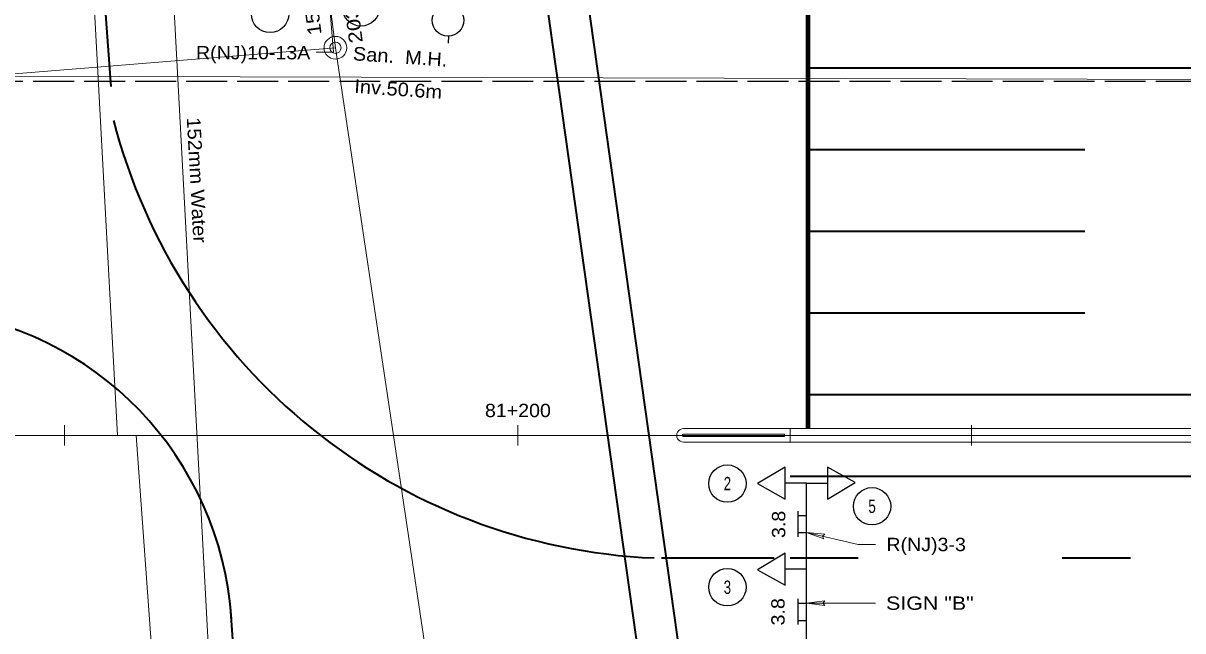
# Model space of a CAD drawing. Extents: x 168203 to 169864, y 223196 to 223870.
# Drawn here: x 168345.6 to 168396.8, y 223625.7 to 223652.4 of the extents above; entities that cross this region are included whole.
import ezdxf
from ezdxf.enums import TextEntityAlignment as Align

# ---------------------------------------------------------------- set-up
doc = ezdxf.new("R2010")
doc.units = 0
doc.header["$LTSCALE"] = 0.3
doc.linetypes.add('LONG_DASHED', pattern=[7.5, 6, -1.5])
for name, color, linetype, lineweight in [('1', 7, 'Continuous', 13), ('23', 7, 'Continuous', 25), ('32', 7, 'Continuous', 25), ('36', 7, 'Continuous', 35), ('6', 7, 'Continuous', 25), ('8', 7, 'Continuous', 25)]:
    doc.layers.add(name, color=color, linetype=linetype, lineweight=lineweight)

msp = doc.modelspace()

# ---------------------------------------------------------------- linework, layer by layer
at = {"layer": '1'}
for p, q in [((168349.7975, 223634.2675), (168346.0287, 223703.2124)), ((168347.4514, 223634.7175), (168347.4514, 223633.8175)), ((168367.4514, 223634.7175), (168367.4514, 223633.8175)), ((168387.4514, 223634.7175), (168387.4514, 223633.8175)), ((168298.0344, 223634.2675), (168427.4519, 223634.2676)), ((168355.9956, 223559.8648), (168350.6186, 223634.2675)), ((168374.7516, 223634.5668), (168379.4515, 223634.5676)), ((168374.7517, 223634.3168), (168379.2017, 223634.3176)), ((168374.7517, 223634.2167), (168379.2017, 223634.2175)), ((168379.2017, 223634.3176), (168379.2017, 223634.2175)), ((168379.4515, 223634.5676), (168379.4516, 223633.9676)), ((168379.4515, 223634.5676), (168427.4519, 223634.5676)), ((168374.7517, 223633.9668), (168379.4515, 223633.9676)), ((168379.4515, 223633.9676), (168427.4519, 223633.9677))]:
    msp.add_line(p, q, dxfattribs=at)
for radius in [0.3, 0.05]:
    msp.add_arc((168374.7516, 223634.2668), radius, 90, 270.0191, dxfattribs=at)
at = {"layer": '23', "lineweight": 13}
for p, q in [((168357.586, 223554.132), (168349.5897, 223703.4835)), ((168359.4003, 223651.3453), (168352.7333, 223703.4586)), ((168359.4003, 223651.3453), (168318.5983, 223648.0208)), ((168359.4003, 223651.3453), (168367.4305, 223597.8004)), ((168317.2096, 223650.1818), (168433.5316, 223649.8335))]:
    msp.add_line(p, q, dxfattribs=at)
for radius in [0.5, 0.25]:
    msp.add_circle((168359.4003, 223651.3453), radius, dxfattribs=at)
at = {"layer": '32'}
for p, q in [((168380.1659, 223632.1676), (168379.2261, 223632.1676)), ((168379.7863, 223630.9339), (168379.7863, 223629.8044)), ((168379.7863, 223630.7441), (168380.1658, 223630.7441)), ((168379.7863, 223629.9851), (168380.1658, 223629.9851)), ((168380.1659, 223628.3676), (168379.2261, 223628.3676)), ((168379.7864, 223627.0626), (168379.7864, 223625.9331)), ((168379.7864, 223626.8728), (168380.1659, 223626.8728)), ((168379.7864, 223626.1138), (168380.1659, 223626.1138))]:
    msp.add_line(p, q, dxfattribs=at)
at = {"layer": '32', "lineweight": 13}
for p, q in [((168382.4555, 223629.4678), (168380.1658, 223629.9851)), ((168382.4555, 223629.4678), (168383.2142, 223629.4678)), ((168380.1659, 223626.8728), (168383.2142, 223626.8728))]:
    msp.add_line(p, q, dxfattribs=at)
msp.add_lwpolyline([(168358.5538, 223651.1547), (168359.3125, 223651.1547), (168358.8755, 223656.4839)], dxfattribs=at)
at = {"layer": '32'}
for points in [[(168378.0063, 223632.1495), (168379.2261, 223631.4628), (168379.2261, 223632.1676), (168379.2261, 223632.8724)], [(168382.3255, 223632.1857), (168381.1057, 223632.8724), (168381.1057, 223632.1676), (168381.1057, 223631.4628)], [(168378.0063, 223628.3495), (168379.2261, 223627.6628), (168379.2261, 223628.3676), (168379.2261, 223629.0724)]]:
    msp.add_lwpolyline(points, close=True, dxfattribs=at)
msp.add_lwpolyline([(168380.1659, 223613.8676), (168380.1659, 223632.1676), (168381.1057, 223632.1676)], dxfattribs=at)
at = {"layer": '32', "lineweight": 13}
for points in [[(168380.9372, 223629.7089), (168380.1658, 223629.9851), (168380.983, 223629.9116), (168380.8797, 223629.8238)], [(168380.9792, 223626.7734), (168380.1659, 223626.8728), (168380.9792, 223626.9812), (168380.8978, 223626.8728)]]:
    msp.add_lwpolyline(points, close=True, dxfattribs=at)
at = {"layer": '32'}
for centre in [(168356.52, 223652.8356), (168360.5298, 223653.1218), (168376.6839, 223632.1434), (168383.0633, 223631.1445), (168376.6839, 223627.579)]:
    msp.add_circle(centre, 0.8236, dxfattribs=at)
at = {"layer": '36'}
for p, q in [((168349.5082, 223649.6433), (168348.9759, 223657.0092)), ((168374.0279, 223615.7265), (168368.7066, 223653.4676)), ((168375.8367, 223615.7899), (168370.5243, 223653.4676)), ((168380.2468, 223650.4671), (168431.5307, 223650.4672)), ((168380.2468, 223646.8671), (168392.4521, 223646.8671)), ((168380.2469, 223643.2671), (168392.452, 223643.2672)), ((168380.2469, 223639.6672), (168392.4521, 223639.6672)), ((168380.2469, 223636.0672), (168427.4519, 223636.0672)), ((168379.4521, 223632.4672), (168427.4519, 223632.4672)), ((168373.7721, 223628.8671), (168378.7516, 223628.8671)), ((168379.4522, 223628.8671), (168382.4522, 223628.8671)), ((168391.4522, 223628.8671), (168394.4522, 223628.8671)), ((168355.7208, 223613.6203), (168354.7732, 223626.7317))]:
    msp.add_line(p, q, dxfattribs=at)
at = {"layer": '36', "lineweight": 80}
msp.add_line((168380.2469, 223634.5676), (168380.2468, 223653.4676), dxfattribs=at)
at = {"layer": '36'}
for centre, radius, start, end in [((168374.5533, 223654.6027), 25.759, 194.51362, 267.55708), ((168340.2591, 223625.2498), 14.5836, 3.68649, 84.22505)]:
    msp.add_arc(centre, radius, start, end, dxfattribs=at)
at = {"layer": '6', "linetype": 'LONG_DASHED'}
msp.add_line((168332.5747, 223649.8768), (168431.2156, 223649.8769), dxfattribs=at)
at = {"layer": '8'}
msp.add_line((168364.3808, 223651.861), (168364.3744, 223651.5478), dxfattribs=at)
msp.add_circle((168364.3648, 223652.5542), 0.6965, dxfattribs=at)

# ---------------------------------------------------------------- texts
at = {"layer": '1', "width": 1.1}
msp.add_text('81+200', height=0.5873, dxfattribs=at).set_placement((168367.4477, 223635.0724), align=Align.CENTER)
at = {"layer": '23'}
for s, rotation, width, p in [('152mm Force & ', 97.692, 1.15, (168358.3408, 223655.3191)), ('203mm Sanitary', 97.692, 1.2, (168360.1428, 223655.0662)), ('San.  M.H.', 356.065, 1.1, (168362.2352, 223650.6533)), ('Inv.50.6m', 356.065, 1.1, (168362.1529, 223649.2238)), ('152mm Water', 273.065, 1.1, (168352.9947, 223645.4967))]:
    msp.add_text(s, height=0.6, rotation=rotation, dxfattribs=dict(at, width=width)).set_placement(p, align=Align.CENTER)
at = {"layer": '32'}
for s, width, p in [('R(NJ)10-13A', 1.1, (168355.7725, 223650.8348)), ('2', 0.75, (168376.684, 223631.8498)), ('5', 0.75, (168383.0634, 223630.8509)), ('R(NJ)3-3', 1.1, (168385.448, 223629.1678)), ('3', 0.75, (168376.684, 223627.2854)), ('SIGN "B"', 1.2, (168385.6128, 223626.5829))]:
    msp.add_text(s, height=0.5873, dxfattribs=dict(at, width=width)).set_placement(p, align=Align.CENTER)
at = {"layer": '32', "width": 1.1}
for p in [(168379.2374, 223630.3457), (168379.2067, 223626.4965)]:
    msp.add_text('3.8', height=0.5873, rotation=90, dxfattribs=at).set_placement(p, align=Align.CENTER)

doc.saveas('drawing.dxf')
